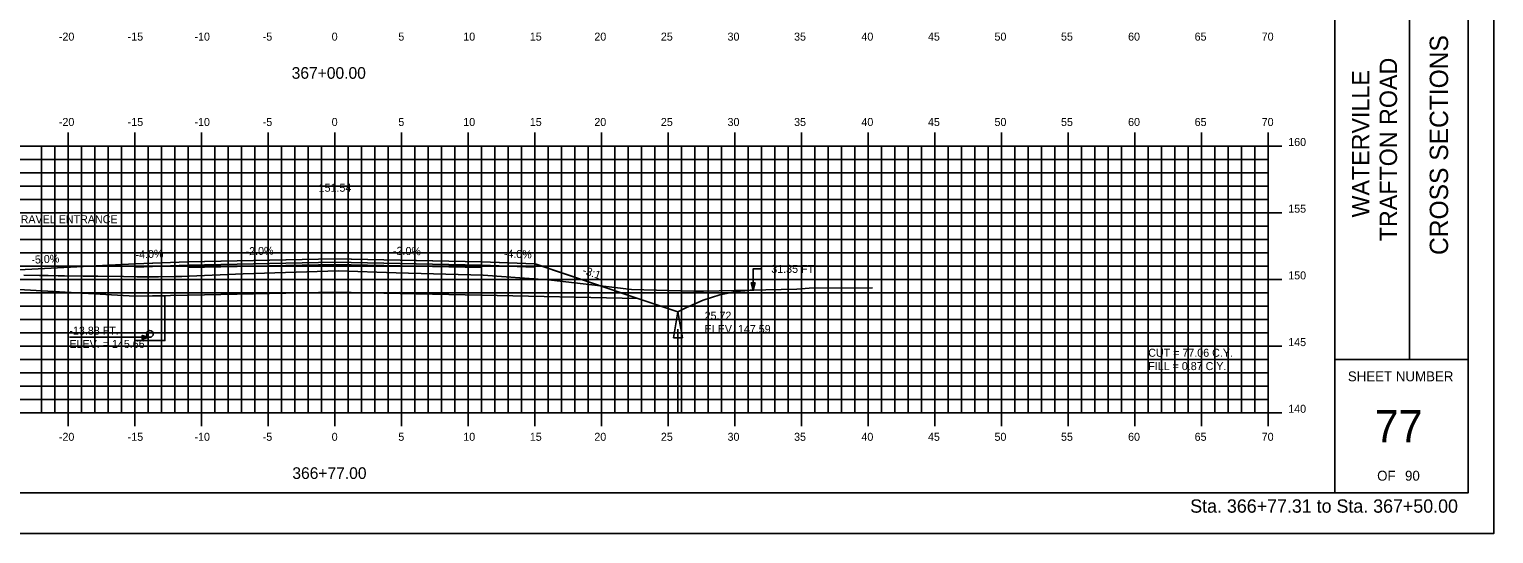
# Model space of a CAD drawing. Extents: x 1147633 to 1147803, y 608981 to 609091.
# Drawn here: x 1147693.5 to 1147803.4, y 608981.3 to 609019.1 of the extents above; entities that cross this region are included whole.
import ezdxf

# ---------------------------------------------------------------- set-up
doc = ezdxf.new("R2010")
doc.units = 0
for name, color, linetype in [('ANNOTATION', 7, 'Continuous'), ('BORDER', 7, 'Continuous'), ('D_Drainage_Ditch_Line', 7, 'Continuous'), ('D_Drainage_Underdrain', 7, 'Continuous'), ('D_Drainage_Underdrain_06in', 7, 'Continuous'), ('D_Roadway_Centerline', 7, 'Continuous'), ('D_Roadway_Centerline_Text', 7, 'Continuous'), ('D_Roadway_Edge_Shoulder', 7, 'Continuous'), ('D_Roadway_Edge_TW', 7, 'Continuous'), ('D_Roadway_Pavement', 7, 'Continuous'), ('D_Roadway_SlopeLines', 7, 'Continuous'), ('D_Roadway_SubGrade', 7, 'Continuous'), ('D_Text_Standard', 7, 'Continuous'), ('H_V ANNOTATION', 7, 'Continuous'), ('HIGHWAY_TITLE', 7, 'Continuous'), ('MAJOR', 7, 'Continuous'), ('MINOR', 7, 'Continuous'), ('PLOT BOUNDARY', 7, 'Continuous'), ('S_Roadway_Centerline', 7, 'Continuous')]:
    doc.layers.add(name, color=color, linetype=linetype)

msp = doc.modelspace()

# ---------------------------------------------------------------- linework, layer by layer
msp.add_lwpolyline([(1147688.37, 609000.84), (1147688.37, 609000.84), (1147701.45, 609001.5), (1147701.46, 609001.5), (1147705.45, 609001.66), (1147705.46, 609001.66), (1147716.45, 609001.88), (1147716.46, 609001.88), (1147727.45, 609001.66), (1147727.46, 609001.66), (1147731.45, 609001.5), (1147731.46, 609001.5), (1147739.18, 608998.92), (1147742.18, 608997.92), (1147742.81, 608998.24), (1147744.06, 608998.79), (1147745.31, 608999.19), (1147746.56, 608999.44), (1147747.81, 608999.54)])
at = {"layer": 'BORDER'}
for p, q in [((1147791.45, 608984.34), (1147791.45, 609089.34)), ((1147797.05, 608994.34), (1147797.05, 609029.34)), ((1147791.45, 608994.34), (1147801.45, 608994.34))]:
    msp.add_line(p, q, dxfattribs=at)
msp.add_lwpolyline([(1147641.45, 608984.34), (1147801.45, 608984.34), (1147801.45, 609089.34), (1147641.45, 609089.34)], close=True, dxfattribs=at)
at = {"layer": 'D_Drainage_Ditch_Line'}
msp.add_line((1147742.18, 608996.61), (1147742.18, 608990.37), dxfattribs=at)
msp.add_lwpolyline([(1147742.51, 608995.96), (1147741.85, 608995.96), (1147742.18, 608997.92)], close=True, dxfattribs=at)
at = {"layer": 'D_Drainage_Underdrain'}
msp.add_lwpolyline([(1147701.45, 608999.08), (1147701.45, 608995.75), (1147703.7, 608995.75), (1147703.7, 608999.12)], close=True, dxfattribs=at)
at = {"layer": 'D_Drainage_Underdrain_06in'}
msp.add_lwpolyline([(1147702.58, 608996.5), (1147702.66, 608996.49), (1147702.73, 608996.45), (1147702.78, 608996.4), (1147702.82, 608996.33), (1147702.83, 608996.25), (1147702.82, 608996.17), (1147702.78, 608996.1), (1147702.73, 608996.05), (1147702.66, 608996.01), (1147702.58, 608996), (1147702.5, 608996.01), (1147702.43, 608996.05), (1147702.38, 608996.1), (1147702.34, 608996.17), (1147702.33, 608996.25), (1147702.34, 608996.33), (1147702.38, 608996.4), (1147702.43, 608996.45), (1147702.5, 608996.49)], close=True, dxfattribs=at)
at = {"layer": 'D_Roadway_Edge_Shoulder'}
for points in [[(1147705.45, 609001.66), (1147701.45, 609001.5), (1147701.45, 609001.25), (1147705.45, 609001.41)], [(1147727.45, 609001.66), (1147731.45, 609001.5), (1147731.45, 609001.25), (1147727.45, 609001.41)]]:
    msp.add_lwpolyline(points, close=True, dxfattribs=at)
at = {"layer": 'D_Roadway_Edge_TW'}
msp.add_lwpolyline([(1147705.45, 609001.41), (1147705.45, 609001.66), (1147716.45, 609001.88), (1147727.45, 609001.66), (1147727.45, 609001.41), (1147716.45, 609001.63)], close=True, dxfattribs=at)
at = {"layer": 'D_Roadway_Pavement'}
msp.add_lwpolyline([(1147705.45, 609001.24), (1147705.45, 609001.41), (1147716.45, 609001.63), (1147727.45, 609001.41), (1147727.45, 609001.24), (1147716.45, 609001.46)], close=True, dxfattribs=at)
at = {"layer": 'D_Roadway_SlopeLines'}
for points in [[(1147742.18, 608997.92), (1147742.81, 608998.24), (1147744.06, 608998.79), (1147745.31, 608999.19), (1147746.56, 608999.44), (1147747.81, 608999.54)], [(1147739.18, 608998.92), (1147742.18, 608997.92)]]:
    msp.add_lwpolyline(points, dxfattribs=at)
at = {"layer": 'D_Roadway_SubGrade'}
for points in [[(1147688.37, 608999.84), (1147701.45, 608999.08), (1147705.45, 608999.16), (1147705.45, 609001.24), (1147705.45, 609001.41), (1147701.45, 609001.25), (1147701.45, 609001.5), (1147688.37, 609000.84)], [(1147705.45, 608999.16), (1147705.45, 609001.24), (1147716.45, 609001.46), (1147727.45, 609001.24), (1147727.45, 608999.16), (1147716.45, 608999.38)], [(1147727.45, 609001.24), (1147727.45, 609001.41), (1147731.45, 609001.25), (1147731.45, 609001.5), (1147731.45, 609001.5), (1147739.18, 608998.92), (1147727.45, 608999.16)]]:
    msp.add_lwpolyline(points, close=True, dxfattribs=at)
at = {"layer": 'D_Text_Standard'}
msp.add_line((1147696.54, 608996), (1147700.95, 608996), dxfattribs=at)
for points in [[(1147747.81, 608999.49), (1147747.82, 609001.13), (1147748.5, 609001.13)], [(1147702.58, 608996), (1147701.63, 608996), (1147700.95, 608996)]]:
    msp.add_lwpolyline(points, dxfattribs=at)
for points in [[(1147747.81, 608999.49), (1147747.67, 609000.07), (1147747.96, 609000.07)], [(1147702.58, 608996), (1147702, 608995.85), (1147702, 608996.14)]]:
    msp.add_lwpolyline(points, close=True, dxfattribs=at)
at = {"layer": 'MAJOR'}
for p, q in [((1147696.45, 609011.34), (1147696.45, 609010.34)), ((1147701.45, 609011.34), (1147701.45, 609010.34)), ((1147706.45, 609011.34), (1147706.45, 609010.34)), ((1147711.45, 609011.34), (1147711.45, 609010.34)), ((1147716.45, 609011.34), (1147716.45, 609010.34)), ((1147721.45, 609011.34), (1147721.45, 609010.34)), ((1147726.45, 609011.34), (1147726.45, 609010.34)), ((1147731.45, 609011.34), (1147731.45, 609010.34)), ((1147736.45, 609011.34), (1147736.45, 609010.34)), ((1147741.45, 609011.34), (1147741.45, 609010.34)), ((1147746.45, 609011.34), (1147746.45, 609010.34)), ((1147751.45, 609011.34), (1147751.45, 609010.34)), ((1147756.45, 609011.34), (1147756.45, 609010.34)), ((1147761.45, 609011.34), (1147761.45, 609010.34)), ((1147766.45, 609011.34), (1147766.45, 609010.34)), ((1147771.45, 609011.34), (1147771.45, 609010.34)), ((1147776.45, 609011.34), (1147776.45, 609010.34)), ((1147781.45, 609011.34), (1147781.45, 609010.34)), ((1147786.45, 609011.34), (1147786.45, 609010.34)), ((1147646.45, 609010.34), (1147786.45, 609010.34)), ((1147646.45, 609010.34), (1147786.45, 609010.34)), ((1147696.45, 608990.34), (1147696.45, 609010.34)), ((1147701.45, 608990.34), (1147701.45, 609010.34)), ((1147706.45, 608990.34), (1147706.45, 609010.34)), ((1147711.45, 608990.34), (1147711.45, 609010.34)), ((1147716.45, 608990.34), (1147716.45, 609010.34)), ((1147721.45, 608990.34), (1147721.45, 609010.34)), ((1147726.45, 608990.34), (1147726.45, 609010.34)), ((1147731.45, 608990.34), (1147731.45, 609010.34)), ((1147736.45, 608990.34), (1147736.45, 609010.34)), ((1147741.45, 608990.34), (1147741.45, 609010.34)), ((1147746.45, 608990.34), (1147746.45, 609010.34)), ((1147751.45, 608990.34), (1147751.45, 609010.34)), ((1147756.45, 608990.34), (1147756.45, 609010.34)), ((1147761.45, 608990.34), (1147761.45, 609010.34)), ((1147766.45, 608990.34), (1147766.45, 609010.34)), ((1147771.45, 608990.34), (1147771.45, 609010.34)), ((1147776.45, 608990.34), (1147776.45, 609010.34)), ((1147781.45, 608990.34), (1147781.45, 609010.34)), ((1147787.46, 609010.34), (1147785.45, 609010.34)), ((1147786.45, 608990.34), (1147786.45, 609010.34)), ((1147786.45, 608990.34), (1147786.45, 609010.34)), ((1147646.45, 609005.34), (1147786.45, 609005.34)), ((1147787.46, 609005.34), (1147785.45, 609005.34)), ((1147646.45, 609000.34), (1147786.45, 609000.34)), ((1147787.46, 609000.34), (1147785.45, 609000.34)), ((1147646.45, 608995.34), (1147786.45, 608995.34)), ((1147787.46, 608995.34), (1147785.45, 608995.34)), ((1147646.45, 608990.34), (1147786.45, 608990.34)), ((1147646.45, 608990.34), (1147786.45, 608990.34)), ((1147696.45, 608989.33), (1147696.45, 608990.34)), ((1147701.45, 608989.33), (1147701.45, 608990.34)), ((1147706.45, 608989.33), (1147706.45, 608990.34)), ((1147711.45, 608989.33), (1147711.45, 608990.34)), ((1147716.45, 608989.33), (1147716.45, 608990.34)), ((1147721.45, 608989.33), (1147721.45, 608990.34)), ((1147726.45, 608989.33), (1147726.45, 608990.34)), ((1147731.45, 608989.33), (1147731.45, 608990.34)), ((1147736.45, 608989.33), (1147736.45, 608990.34)), ((1147741.45, 608989.33), (1147741.45, 608990.34)), ((1147746.45, 608989.33), (1147746.45, 608990.34)), ((1147751.45, 608989.33), (1147751.45, 608990.34)), ((1147756.45, 608989.33), (1147756.45, 608990.34)), ((1147761.45, 608989.33), (1147761.45, 608990.34)), ((1147766.45, 608989.33), (1147766.45, 608990.34)), ((1147771.45, 608989.33), (1147771.45, 608990.34)), ((1147776.45, 608989.33), (1147776.45, 608990.34)), ((1147781.45, 608989.33), (1147781.45, 608990.34)), ((1147787.46, 608990.34), (1147785.45, 608990.34)), ((1147786.45, 608989.33), (1147786.45, 608990.34))]:
    msp.add_line(p, q, dxfattribs=at)
at = {"layer": 'MINOR'}
for p, q in [((1147694.45, 608990.34), (1147694.45, 609010.34)), ((1147695.45, 608990.34), (1147695.45, 609010.34)), ((1147697.45, 608990.34), (1147697.45, 609010.34)), ((1147698.45, 608990.34), (1147698.45, 609010.34)), ((1147699.45, 608990.34), (1147699.45, 609010.34)), ((1147700.45, 608990.34), (1147700.45, 609010.34)), ((1147702.45, 608990.34), (1147702.45, 609010.34)), ((1147703.45, 608990.34), (1147703.45, 609010.34)), ((1147704.45, 608990.34), (1147704.45, 609010.34)), ((1147705.45, 608990.34), (1147705.45, 609010.34)), ((1147707.45, 608990.34), (1147707.45, 609010.34)), ((1147708.45, 608990.34), (1147708.45, 609010.34)), ((1147709.45, 608990.34), (1147709.45, 609010.34)), ((1147710.45, 608990.34), (1147710.45, 609010.34)), ((1147712.45, 608990.34), (1147712.45, 609010.34)), ((1147713.45, 608990.34), (1147713.45, 609010.34)), ((1147714.45, 608990.34), (1147714.45, 609010.34)), ((1147715.45, 608990.34), (1147715.45, 609010.34)), ((1147717.45, 608990.34), (1147717.45, 609010.34)), ((1147718.45, 608990.34), (1147718.45, 609010.34)), ((1147719.45, 608990.34), (1147719.45, 609010.34)), ((1147720.45, 608990.34), (1147720.45, 609010.34)), ((1147722.45, 608990.34), (1147722.45, 609010.34)), ((1147723.45, 608990.34), (1147723.45, 609010.34)), ((1147724.45, 608990.34), (1147724.45, 609010.34)), ((1147725.45, 608990.34), (1147725.45, 609010.34)), ((1147727.45, 608990.34), (1147727.45, 609010.34)), ((1147728.45, 608990.34), (1147728.45, 609010.34)), ((1147729.45, 608990.34), (1147729.45, 609010.34)), ((1147730.45, 608990.34), (1147730.45, 609010.34)), ((1147732.45, 608990.34), (1147732.45, 609010.34)), ((1147733.45, 608990.34), (1147733.45, 609010.34)), ((1147734.45, 608990.34), (1147734.45, 609010.34)), ((1147735.45, 608990.34), (1147735.45, 609010.34)), ((1147737.45, 608990.34), (1147737.45, 609010.34)), ((1147738.45, 608990.34), (1147738.45, 609010.34)), ((1147739.45, 608990.34), (1147739.45, 609010.34)), ((1147740.45, 608990.34), (1147740.45, 609010.34)), ((1147742.45, 608990.34), (1147742.45, 609010.34)), ((1147743.45, 608990.34), (1147743.45, 609010.34)), ((1147744.45, 608990.34), (1147744.45, 609010.34)), ((1147745.45, 608990.34), (1147745.45, 609010.34)), ((1147747.45, 608990.34), (1147747.45, 609010.34)), ((1147748.45, 608990.34), (1147748.45, 609010.34)), ((1147749.45, 608990.34), (1147749.45, 609010.34)), ((1147750.45, 608990.34), (1147750.45, 609010.34)), ((1147752.45, 608990.34), (1147752.45, 609010.34)), ((1147753.45, 608990.34), (1147753.45, 609010.34)), ((1147754.45, 608990.34), (1147754.45, 609010.34)), ((1147755.45, 608990.34), (1147755.45, 609010.34)), ((1147757.45, 608990.34), (1147757.45, 609010.34)), ((1147758.45, 608990.34), (1147758.45, 609010.34)), ((1147759.45, 608990.34), (1147759.45, 609010.34)), ((1147760.45, 608990.34), (1147760.45, 609010.34)), ((1147762.45, 608990.34), (1147762.45, 609010.34)), ((1147763.45, 608990.34), (1147763.45, 609010.34)), ((1147764.45, 608990.34), (1147764.45, 609010.34)), ((1147765.45, 608990.34), (1147765.45, 609010.34)), ((1147767.45, 608990.34), (1147767.45, 609010.34)), ((1147768.45, 608990.34), (1147768.45, 609010.34)), ((1147769.45, 608990.34), (1147769.45, 609010.34)), ((1147770.45, 608990.34), (1147770.45, 609010.34)), ((1147772.45, 608990.34), (1147772.45, 609010.34)), ((1147773.45, 608990.34), (1147773.45, 609010.34)), ((1147774.45, 608990.34), (1147774.45, 609010.34)), ((1147775.45, 608990.34), (1147775.45, 609010.34)), ((1147777.45, 608990.34), (1147777.45, 609010.34)), ((1147778.45, 608990.34), (1147778.45, 609010.34)), ((1147779.45, 608990.34), (1147779.45, 609010.34)), ((1147780.45, 608990.34), (1147780.45, 609010.34)), ((1147782.45, 608990.34), (1147782.45, 609010.34)), ((1147783.45, 608990.34), (1147783.45, 609010.34)), ((1147784.45, 608990.34), (1147784.45, 609010.34)), ((1147785.45, 608990.34), (1147785.45, 609010.34)), ((1147646.45, 609009.34), (1147786.45, 609009.34)), ((1147786.45, 609009.34), (1147785.45, 609009.34)), ((1147646.45, 609008.34), (1147786.45, 609008.34)), ((1147786.45, 609008.34), (1147785.45, 609008.34)), ((1147646.45, 609007.34), (1147786.45, 609007.34)), ((1147786.45, 609007.34), (1147785.45, 609007.34)), ((1147646.45, 609006.34), (1147786.45, 609006.34)), ((1147786.45, 609006.34), (1147785.45, 609006.34)), ((1147646.45, 609004.34), (1147786.45, 609004.34)), ((1147786.45, 609004.34), (1147785.45, 609004.34)), ((1147646.45, 609003.34), (1147786.45, 609003.34)), ((1147646.45, 609002.34), (1147786.45, 609002.34)), ((1147786.45, 609003.34), (1147785.45, 609003.34)), ((1147786.45, 609002.34), (1147785.45, 609002.34)), ((1147646.45, 609001.34), (1147786.45, 609001.34)), ((1147786.45, 609001.34), (1147785.45, 609001.34)), ((1147646.45, 608999.34), (1147786.45, 608999.34)), ((1147786.45, 608999.34), (1147785.45, 608999.34)), ((1147646.45, 608998.34), (1147786.45, 608998.34)), ((1147786.45, 608998.34), (1147785.45, 608998.34)), ((1147646.45, 608997.34), (1147786.45, 608997.34)), ((1147786.45, 608997.34), (1147785.45, 608997.34)), ((1147646.45, 608996.34), (1147786.45, 608996.34)), ((1147786.45, 608996.34), (1147785.45, 608996.34)), ((1147646.45, 608994.34), (1147786.45, 608994.34)), ((1147786.45, 608994.34), (1147785.45, 608994.34)), ((1147646.45, 608993.34), (1147786.45, 608993.34)), ((1147786.45, 608993.34), (1147785.45, 608993.34)), ((1147646.45, 608992.34), (1147786.45, 608992.34)), ((1147646.45, 608991.34), (1147786.45, 608991.34)), ((1147786.45, 608992.34), (1147785.45, 608992.34)), ((1147786.45, 608991.34), (1147785.45, 608991.34))]:
    msp.add_line(p, q, dxfattribs=at)
at = {"layer": 'PLOT BOUNDARY'}
msp.add_lwpolyline([(1147633.36, 608981.28), (1147803.36, 608981.28), (1147803.36, 609091.28), (1147633.36, 609091.28)], close=True, dxfattribs=at)
at = {"layer": 'S_Roadway_Centerline'}
msp.add_lwpolyline([(1147693.12, 609000.66), (1147694.29, 609000.64), (1147694.94, 609000.62), (1147695.7, 609000.61), (1147696.17, 609000.61), (1147697.58, 609000.59), (1147698.66, 609000.57), (1147700.59, 609000.55), (1147701.62, 609000.54), (1147703.21, 609000.54), (1147704.5, 609000.55), (1147704.98, 609000.56), (1147705.53, 609000.57), (1147709.56, 609000.75), (1147716.72, 609000.98), (1147721.04, 609000.83), (1147727.58, 609000.65), (1147732.39, 609000.3), (1147732.7, 609000.29), (1147737.44, 608999.74), (1147738.7, 608999.59), (1147743.38, 608999.45), (1147743.66, 608999.45), (1147744.1, 608999.47), (1147751.1, 608999.6), (1147752.03, 608999.67), (1147756.77, 608999.71)], dxfattribs=at)

# ---------------------------------------------------------------- texts
at = {"layer": 'ANNOTATION'}
msp.add_text('CONSTRUCT GRAVEL ENTRANCE', height=0.6, dxfattribs=at).set_placement((1147687, 609004.55))
for s, rotation, p in [('-4.0%', 2.2906, (1147701.51, 609001.9)), ('-2.0%', 1.1458, (1147709.76, 609002.15)), ('-2.0%', 358.8542, (1147720.8, 609002.19)), ('-4.0%', 357.7094, (1147729.11, 609001.99)), ('-5.0%', 2.8624, (1147693.7, 609001.51)), ('-3:1', 341.5653, (1147734.97, 609000.78))]:
    msp.add_text(s, height=0.6, rotation=rotation, dxfattribs=at).set_placement(p)
at = {"layer": 'BORDER'}
msp.add_text('CROSS SECTIONS', height=1.3779, rotation=90, dxfattribs=at).set_placement((1147799.94, 609002.17))
for s, height, p in [('SHEET NUMBER', 0.7453, (1147792.42, 608992.7)), ('77', 2.419, (1147794.43, 608988.12)), ('OF', 0.745, (1147794.62, 608985.25)), ('90', 0.745, (1147796.71, 608985.25))]:
    msp.add_text(s, height=height, dxfattribs=at).set_placement(p)
at = {"layer": 'D_Roadway_Centerline'}
for s, p in [('C', (1147716.45, 609001.88)), ('L', (1147716.45, 609001.87))]:
    msp.add_text(s, height=0.0146, dxfattribs=at).set_placement(p)
at = {"layer": 'D_Roadway_Centerline_Text'}
msp.add_text('151.54', height=0.6, dxfattribs=at).set_placement((1147715.23, 609006.91))
at = {"layer": 'D_Text_Standard'}
for s, p in [('31.35 FT', (1147749.18, 609000.83)), ('25.72', (1147744.18, 608997.32)), ('-13.88 FT.', (1147696.54, 608996.2)), ('ELEV. 147.59', (1147744.18, 608996.32)), ('ELEV. = 145.66', (1147696.54, 608995.2)), ('CUT = 77.06 C.Y.', (1147777.45, 608994.54)), ('FILL = 0.87 C.Y.', (1147777.45, 608993.54))]:
    msp.add_text(s, height=0.6, dxfattribs=at).set_placement(p)
at = {"layer": 'H_V ANNOTATION'}
for s, height, p in [('-20', 0.6, (1147695.75, 609018.24)), ('-15', 0.6, (1147700.91, 609018.24)), ('-10', 0.6, (1147705.92, 609018.24)), ('-5', 0.6, (1147711.04, 609018.24)), ('0', 0.6, (1147716.21, 609018.24)), ('5', 0.6, (1147721.21, 609018.24)), ('10', 0.6, (1147726.08, 609018.24)), ('15', 0.6, (1147731.07, 609018.24)), ('20', 0.6, (1147735.91, 609018.24)), ('25', 0.6, (1147740.9, 609018.24)), ('30', 0.6, (1147745.9, 609018.24)), ('35', 0.6, (1147750.89, 609018.24)), ('40', 0.6, (1147755.94, 609018.24)), ('45', 0.6, (1147760.93, 609018.24)), ('50', 0.6, (1147765.92, 609018.24)), ('55', 0.6, (1147770.91, 609018.24)), ('60', 0.6, (1147775.94, 609018.24)), ('65', 0.6, (1147780.93, 609018.24)), ('70', 0.6, (1147785.96, 609018.24)), ('367+00.00', 0.875, (1147713.21, 609015.38)), ('-20', 0.6, (1147695.75, 609011.84)), ('-15', 0.6, (1147700.91, 609011.84)), ('-10', 0.6, (1147705.92, 609011.84)), ('-5', 0.6, (1147711.04, 609011.84)), ('0', 0.6, (1147716.21, 609011.84)), ('5', 0.6, (1147721.21, 609011.84)), ('10', 0.6, (1147726.08, 609011.84)), ('15', 0.6, (1147731.07, 609011.84)), ('20', 0.6, (1147735.91, 609011.84)), ('25', 0.6, (1147740.9, 609011.84)), ('30', 0.6, (1147745.9, 609011.84)), ('35', 0.6, (1147750.89, 609011.84)), ('40', 0.6, (1147755.94, 609011.84)), ('45', 0.6, (1147760.93, 609011.84)), ('50', 0.6, (1147765.92, 609011.84)), ('55', 0.6, (1147770.91, 609011.84)), ('60', 0.6, (1147775.94, 609011.84)), ('65', 0.6, (1147780.93, 609011.84)), ('70', 0.6, (1147785.96, 609011.84)), ('160', 0.6, (1147787.95, 609010.34)), ('155', 0.6, (1147787.95, 609005.34)), ('150', 0.6, (1147787.95, 609000.34)), ('145', 0.6, (1147787.95, 608995.34)), ('140', 0.6, (1147787.95, 608990.34)), ('-20', 0.6, (1147695.75, 608988.24)), ('-15', 0.6, (1147700.91, 608988.24)), ('-10', 0.6, (1147705.92, 608988.24)), ('-5', 0.6, (1147711.04, 608988.24)), ('0', 0.6, (1147716.21, 608988.24)), ('5', 0.6, (1147721.21, 608988.24)), ('10', 0.6, (1147726.08, 608988.24)), ('15', 0.6, (1147731.07, 608988.24)), ('20', 0.6, (1147735.91, 608988.24)), ('25', 0.6, (1147740.9, 608988.24)), ('30', 0.6, (1147745.9, 608988.24)), ('35', 0.6, (1147750.89, 608988.24)), ('40', 0.6, (1147755.94, 608988.24)), ('45', 0.6, (1147760.93, 608988.24)), ('50', 0.6, (1147765.92, 608988.24)), ('55', 0.6, (1147770.91, 608988.24)), ('60', 0.6, (1147775.94, 608988.24)), ('65', 0.6, (1147780.93, 608988.24)), ('70', 0.6, (1147785.96, 608988.24)), ('366+77.00', 0.875, (1147713.26, 608985.38)), ('Sta. 366+77.31 to Sta. 367+50.00', 1.0002, (1147780.6, 608982.85))]:
    msp.add_text(s, height=height, dxfattribs=at).set_placement(p)
at = {"layer": 'HIGHWAY_TITLE'}
for s, height, p in [('TRAFTON ROAD', 1.3043, (1147796.11, 609003.2)), ('WATERVILLE', 1.304, (1147794.03, 609004.98))]:
    msp.add_text(s, height=height, rotation=90, dxfattribs=at).set_placement(p)
at = {"layer": 'S_Roadway_Centerline'}
for s, p in [('C', (1147716.72, 609000.98)), ('L', (1147716.72, 609000.97))]:
    msp.add_text(s, height=0.0146, dxfattribs=at).set_placement(p)

doc.saveas('drawing.dxf')
